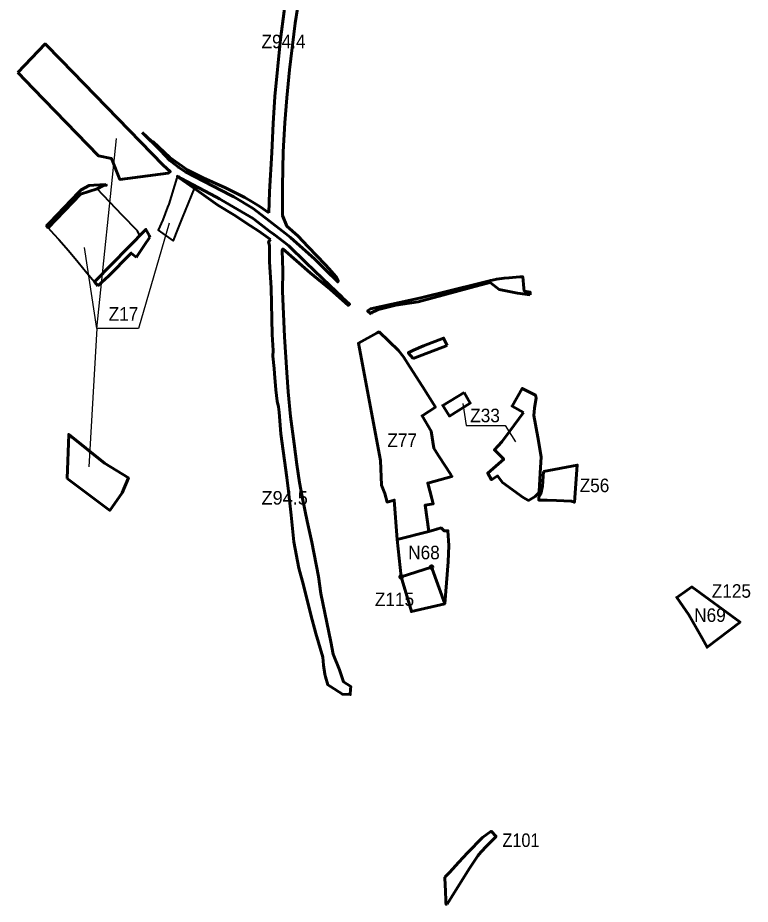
# Model space of a CAD drawing. Extents: x -650277 to -643422, y -1073980 to -1066720.
# Drawn here: x -645817 to -644519, y -1073665 to -1072093 of the extents above; entities that cross this region are included whole.
import ezdxf

# ---------------------------------------------------------------- set-up
doc = ezdxf.new("R2010")
doc.units = 0
doc.header["$LTSCALE"] = 9.6
doc.header["$PDMODE"] = 32
doc.header["$PDSIZE"] = 4.8
for name, color, linetype, lineweight in [('1', 7, 'Continuous', 60), ('15', 7, 'Continuous', 60), ('2', 7, 'Continuous', 40), ('3', 7, 'Continuous', 60), ('42', 7, 'Continuous', 60), ('59', 7, 'Continuous', 25), ('60', 7, 'Continuous', 60), ('63', 7, 'Continuous', 25), ('9', 7, 'Continuous', 60)]:
    doc.layers.add(name, color=color, linetype=linetype, lineweight=lineweight)

msp = doc.modelspace()

# ---------------------------------------------------------------- linework, layer by layer
at = {"layer": '1'}
for points in [[(-645817.219, -1072189.975), (-645768.649, -1072139.283), (-645740.45, -1072168.23), (-645559.34, -1072354.42), (-645546.82, -1072365.72), (-645550.41, -1072368.47), (-645636.37, -1072379.57), (-645650.78, -1072342.73), (-645674, -1072338), (-645789.298, -1072218.833)], [(-645729.36, -1072909.65), (-645654.16, -1072966.3), (-645632.23, -1072935.28), (-645620.92, -1072908.65), (-645663.52, -1072882.58), (-645726.9, -1072831.5)], [(-644536.62, -1073164.33), (-644536.62, -1073164.33), (-644622.03, -1073101.88), (-644622.03, -1073101.88), (-644630.58, -1073107.78), (-644648.95, -1073120.47), (-644627.53, -1073151.26), (-644604.13, -1073193), (-644595.18, -1073208.98)]]:
    msp.add_lwpolyline(points, close=True, dxfattribs=at)
at = {"layer": '15'}
for points in [[(-645661.3, -1072388.74), (-645682.59, -1072389.76), (-645690.37, -1072390.13), (-645705, -1072398.19), (-645708.94, -1072402.11)], [(-645676.53, -1072396.16), (-645676.53, -1072396.16), (-645665.32, -1072390.32), (-645660.16, -1072389.95), (-645661.3, -1072388.74)], [(-645708.94, -1072402.11), (-645760.02, -1072455.94), (-645765.95, -1072462.03), (-645763.06, -1072465.26)], [(-645763.06, -1072465.26), (-645706.039, -1072405.769), (-645676.53, -1072396.16)], [(-645582.84, -1072481.71), (-645584.46, -1072478.58), (-645589.862, -1072468.109), (-645680.87, -1072561.42), (-645675.13, -1072568.36)], [(-645607.07, -1072517.61), (-645605.95, -1072515.95), (-645604.82, -1072514.3), (-645592.9, -1072496.52), (-645583.13, -1072482.13), (-645582.84, -1072481.71)], [(-645675.13, -1072568.36), (-645655.65, -1072550.62), (-645617.87, -1072512.12), (-645615.95, -1072510.16), (-645607.07, -1072517.61)], [(-644919.75, -1072572.43), (-644921.84, -1072552.03), (-644926.81, -1072552.51)], [(-644926.81, -1072552.51), (-644946.57, -1072554.22), (-644954.57, -1072554.43), (-644967.97, -1072556.17), (-644978.56, -1072558.74), (-644999.72, -1072564.24), (-645102.73, -1072589.74), (-645192.06, -1072609.19), (-645197.044, -1072612.821), (-645190.71, -1072618.6)], [(-645147.13, -1072602.79), (-645107.58, -1072596.47), (-644997.92, -1072567.23), (-644979.55, -1072562.44), (-644963.97, -1072574.57)], [(-644963.97, -1072574.57), (-644931.48, -1072581.26), (-644909.02, -1072584.28)], [(-644909.02, -1072584.28), (-644908.59, -1072579.51), (-644919.23, -1072577.46), (-644919.75, -1072572.43)], [(-645190.71, -1072618.6), (-645190.59, -1072616.28), (-645179.6, -1072610.94), (-645177.56, -1072609.89), (-645147.13, -1072602.79)], [(-645056.08, -1072674.07), (-645062.131, -1072660.856), (-645098.016, -1072674.425), (-645115.56, -1072682.406), (-645124.933, -1072686.721), (-645116.11, -1072697.15)], [(-645116.11, -1072697.15), (-645100.9, -1072691.31), (-645056.08, -1072674.07)]]:
    msp.add_lwpolyline(points, dxfattribs=at)
at = {"layer": '2'}
for points in [[(-645503.98, -1072395.64), (-645532.75, -1072375.41), (-645535.05, -1072376.72), (-645549.6, -1072423.39), (-645551.54, -1072428.66), (-645559.92, -1072451.41), (-645568.38, -1072469.68), (-645541.56, -1072488.74), (-645541.09, -1072487.98), (-645533.15, -1072468.21), (-645524.87, -1072447.61)], [(-645600.945, -1072479.473), (-645605.17, -1072470.52), (-645632.1, -1072442.93), (-645632.1, -1072442.93), (-645676.53, -1072396.16), (-645706.039, -1072405.769), (-645763.06, -1072465.26), (-645753.128, -1072476.383), (-645744.38, -1072486.18), (-645726.95, -1072505.7), (-645709.92, -1072526.3), (-645694.51, -1072544.93), (-645680.87, -1072561.42)]]:
    msp.add_lwpolyline(points, close=True, dxfattribs=at)
at = {"layer": '3'}
for points in [[(-644902.18, -1072797.88), (-644901.35, -1072785.36), (-644898.29, -1072766.55), (-644899.2, -1072762.14), (-644922.88, -1072749.97), (-644940.8, -1072781.48), (-644920.46, -1072792.92)], [(-644920.46, -1072792.92), (-644945.2, -1072826.3), (-644959.24, -1072844.92), (-644972.28, -1072859.02), (-644955.49, -1072875.78), (-644983.93, -1072900.24), (-644977.16, -1072912.11), (-644966.57, -1072905.23), (-644957.79, -1072916.73), (-644921.18, -1072943.17), (-644911.87, -1072948.76), (-644900.2, -1072941.67), (-644893.77, -1072935.88), (-644892.86, -1072932.6), (-644891.2, -1072900.09), (-644889.11, -1072871.66), (-644895.32, -1072836.6), (-644902.18, -1072797.88)], [(-645137.5, -1073083.97), (-645119.34, -1073145.61), (-645060.1, -1073131.68), (-645082.6, -1073069.93), (-645083.681, -1073066.962)]]:
    msp.add_lwpolyline(points, dxfattribs=at)
for points in [[(-645025.61, -1072757.17), (-645063.6, -1072780.26), (-645051.94, -1072799.21), (-645015.02, -1072776.01)], [(-645054.12, -1073057.62), (-645052.94, -1073028.58), (-645054.44, -1073002.54), (-645060.95, -1073002.68), (-645066.66, -1072997.3), (-645074.333, -1072999.365), (-645088.62, -1073003.45), (-645144.37, -1073017.64), (-645137.5, -1073083.97), (-645083.681, -1073066.962), (-645082.6, -1073069.93), (-645060.1, -1073131.68)]]:
    msp.add_lwpolyline(points, close=True, dxfattribs=at)
for p in [(-645083.681, -1073066.962), (-645137.5, -1073083.97)]:
    msp.add_point(p, dxfattribs=at)
at = {"layer": '42'}
msp.add_lwpolyline([(-645817.219, -1072189.975), (-645768.649, -1072139.283), (-645740.45, -1072168.23), (-645559.34, -1072354.42), (-645546.82, -1072365.72), (-645550.41, -1072368.47), (-645636.37, -1072379.57), (-645650.78, -1072342.73), (-645674, -1072338), (-645789.298, -1072218.833)], close=True, dxfattribs=at)
at = {"layer": '59'}
for points in [[(-645549, -1072457), (-645603, -1072644), (-645677, -1072644)], [(-645677, -1072644), (-645677, -1072644), (-645699, -1072500)]]:
    msp.add_lwpolyline(points, dxfattribs=at)
at = {"layer": '60'}
for points in [[(-645339.904, -1072462.677), (-645347.551, -1072443.527), (-645347.677, -1072391.355), (-645346.62, -1072330.914), (-645343.458, -1072278.998), (-645339.908, -1072235.158), (-645335.367, -1072185.207), (-645325.498, -1072102.789), (-645309.01, -1071998.147), (-645285.617, -1071875.733), (-645244.798, -1071696.585), (-645235.793, -1071663.703), (-645230.436, -1071634.261), (-645227.905, -1071625.277), (-645222.48, -1071606.08)], [(-645313.153, -1071883.081), (-645326.343, -1071952.807), (-645334.118, -1072001.954), (-645339.455, -1072031.565), (-645344.819, -1072081.225), (-645351.358, -1072130.815), (-645361.317, -1072232.824), (-645364.435, -1072280.268), (-645366.951, -1072331.609), (-645370.624, -1072401.447), (-645372.228, -1072438.764)], [(-645372.228, -1072438.764), (-645387.894, -1072427.453), (-645401.441, -1072419.033), (-645414.631, -1072411.611), (-645448.831, -1072394.325), (-645488.64, -1072376.782), (-645515.437, -1072363.447), (-645547.593, -1072340.827), (-645577.33, -1072312.704), (-645579.217, -1072312.425), (-645596.405, -1072296.114)], [(-645596.405, -1072296.114), (-645564.4, -1072328.61), (-645547.72, -1072346.19), (-645532.07, -1072358.01), (-645531.65, -1072358.29), (-645528.27, -1072360.53), (-645519.57, -1072366.3), (-645438.64, -1072408.1)], [(-645533.08, -1072373.71), (-645534.3, -1072374.33), (-645532.75, -1072375.41), (-645503.98, -1072395.64)], [(-645370.226, -1072471.736), (-645396.94, -1072451.44), (-645400.12, -1072449.03), (-645456.52, -1072415.6), (-645459.31, -1072413.95), (-645465.793, -1072410.498), (-645527.33, -1072377.73), (-645533.08, -1072373.71)], [(-645503.98, -1072395.64), (-645462.65, -1072425.01), (-645462.651, -1072425.011), (-645462.646, -1072425.015)], [(-645438.64, -1072408.1), (-645437.6, -1072408.64), (-645434.19, -1072410.67), (-645399.77, -1072431.12), (-645371.356, -1072453.119), (-645342.284, -1072475.625)], [(-645462.646, -1072425.015), (-645433.91, -1072442.56), (-645404.64, -1072461.72), (-645389.731, -1072471.612), (-645369.364, -1072485.931)], [(-645345.079, -1072490.836), (-645362.81, -1072477.37), (-645370.226, -1072471.736)], [(-645290.76, -1072520.92), (-645271.74, -1072539.96), (-645249.9, -1072561.25), (-645248.967, -1072559.511), (-645252.768, -1072552.178), (-645265.009, -1072538.358), (-645272.276, -1072530.154), (-645302.303, -1072499.014), (-645320.805, -1072479.495), (-645339.904, -1072462.677)], [(-645369.364, -1072485.931), (-645372.72, -1072490.314), (-645370.928, -1072496.619), (-645370.755, -1072525.734), (-645368.173, -1072571.881), (-645366.022, -1072654.462), (-645364.524, -1072682.575), (-645364.786, -1072692.977), (-645362.708, -1072714.781)], [(-645342.284, -1072475.625), (-645333.62, -1072482.33), (-645290.76, -1072520.92)], [(-645338.023, -1072755.969), (-645339.96, -1072721.587), (-645344.152, -1072658.857), (-645347.795, -1072577.893), (-645347.214, -1072540.97), (-645348.253, -1072505.583), (-645347.292, -1072502.877), (-645298.498, -1072545.352)], [(-645242, -1072588.6), (-645263.7, -1072567.8), (-645276.93, -1072555.11), (-645306.46, -1072527.08), (-645336.33, -1072497.48), (-645336.887, -1072497.057), (-645345.079, -1072490.836)], [(-645298.498, -1072545.352), (-645263.217, -1072574.314), (-645230.845, -1072602.888), (-645228.96, -1072600.865), (-645241.87, -1072588.722), (-645242, -1072588.6)], [(-645362.708, -1072714.781), (-645361.874, -1072723.527), (-645359.76, -1072752.865), (-645357.272, -1072772.771), (-645355.121, -1072782.993)], [(-645317.65, -1072916.642), (-645322.284, -1072885.085), (-645327.091, -1072848.387), (-645333.718, -1072799.987), (-645338.023, -1072755.969)], [(-645355.121, -1072782.993), (-645354.019, -1072792.454), (-645350.822, -1072830.388), (-645340.345, -1072908.029), (-645337.34, -1072932.073), (-645332.517, -1072974.538), (-645327.554, -1073022.214)], [(-645304.24, -1072985.372), (-645311.772, -1072947.945), (-645317.65, -1072916.642)], [(-645257.842, -1073221.36), (-645262.388, -1073199.409), (-645279.878, -1073113.356), (-645284.269, -1073083.286), (-645295.788, -1073022.556), (-645304.24, -1072985.372)], [(-645327.554, -1073022.214), (-645319.052, -1073068.6), (-645310.558, -1073098.946), (-645297.395, -1073151.294), (-645288.647, -1073184.518), (-645276.125, -1073226.571), (-645275.269, -1073240.71), (-645272.747, -1073256.762), (-645271.518, -1073261.16), (-645267.525, -1073275.443), (-645263.03, -1073278.25), (-645241.72, -1073292.2), (-645227.744, -1073292.736), (-645227.199, -1073283.366), (-645226.847, -1073278.345), (-645239.9, -1073270.025), (-645247.051, -1073248.736), (-645257.842, -1073221.36)]]:
    msp.add_lwpolyline(points, dxfattribs=at)
at = {"layer": '63'}
for q in [(-645642, -1072307), (-645691, -1072889)]:
    msp.add_line((-645677, -1072644), q, dxfattribs=at)
msp.add_lwpolyline([(-645027.959, -1072776.842), (-645022, -1072816), (-644953, -1072816), (-644935, -1072845)], dxfattribs=at)
at = {"layer": '9'}
for points in [[(-645144.37, -1073017.64), (-645088.62, -1073003.45), (-645095.04, -1072957.07), (-645080.61, -1072954.43), (-645083.13, -1072944.94), (-645090.34, -1072917.86), (-645047.42, -1072906.05), (-645050.6, -1072901.03), (-645069.55, -1072872.12), (-645071.87, -1072868.45), (-645079.81, -1072855.89), (-645084.47, -1072825.67), (-645100.27, -1072798.46), (-645076.66, -1072783.06), (-645099.58, -1072746.945), (-645121.96, -1072711.68), (-645133.26, -1072694.17), (-645142.1, -1072682.57), (-645176.757, -1072649.968), (-645180.05, -1072651.77), (-645213.34, -1072669.98), (-645174.13, -1072877.93), (-645172.28, -1072921.42), (-645166.48, -1072936.5), (-645162.379, -1072951.55), (-645149.84, -1072948.13)], [(-644884.94, -1072897.19), (-644886.98, -1072923.48), (-644889.65, -1072936.67), (-644893.37, -1072942.61), (-644893.59, -1072947.97), (-644878.86, -1072948.42), (-644861.93, -1072948.94), (-644835.99, -1072949.74), (-644830.25, -1072951.9), (-644825.25, -1072885.96)]]:
    msp.add_lwpolyline(points, close=True, dxfattribs=at)
for points in [[(-645056.06, -1073664.2), (-645043.35, -1073644.04), (-645015.55, -1073599.96), (-645001.267, -1073578.582), (-644996.41, -1073571.97), (-644985.66, -1073560.69), (-644969.117, -1073544.254), (-644977.924, -1073535.072), (-644993.044, -1073546.324), (-645020.11, -1073573.585), (-645035.303, -1073590.199), (-645051.513, -1073608.124), (-645060.009, -1073616.53)], [(-645060.009, -1073616.53), (-645059.35, -1073631.3), (-645058.96, -1073640.09), (-645058.65, -1073647), (-645058.42, -1073652.18), (-645058.01, -1073661.37), (-645057.87, -1073664.55), (-645056.06, -1073664.2)]]:
    msp.add_lwpolyline(points, dxfattribs=at)

# ---------------------------------------------------------------- texts
at = {"layer": '59', "width": 0.95}
msp.add_text('Z17', height=24, dxfattribs=at).set_placement((-645656, -1072630))
at = {"layer": '63'}
for s, width, p in [('Z94.4', 0.95, (-645385, -1072147)), ('Z33', 0.95, (-645015, -1072810)), ('Z77', 0.95, (-645162, -1072854)), ('Z56', 0.95, (-644821, -1072934)), ('N68', 0.95, (-645125, -1073053)), ('Z125', 0.95, (-644586.786, -1073121.127)), ('Z115', 0.95, (-645184, -1073136)), ('N69', 0.95, (-644618, -1073164)), ('Z101', 0.9, (-644958, -1073563))]:
    msp.add_text(s, height=24, dxfattribs=dict(at, width=width)).set_placement(p)
msp.add_text('Z94.5', height=24, dxfattribs=at).set_placement((-645385, -1072956))

doc.saveas('drawing.dxf')
